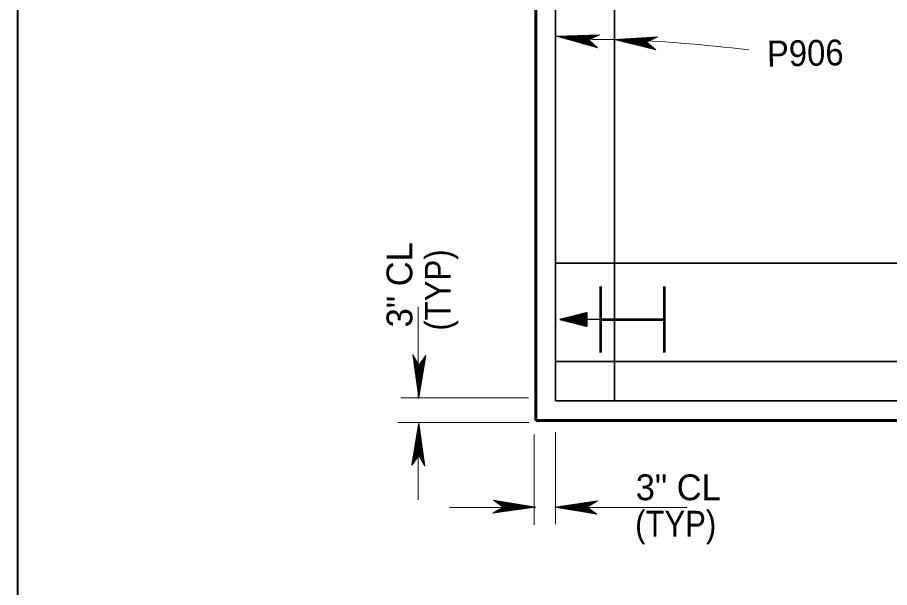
# Model space of a CAD drawing. Extents: x 144 to 252, y 360 to 425.
# Drawn here: x 149.81 to 160.9, y 367.66 to 374.91 of the extents above; entities that cross this region are included whole.
import ezdxf
from ezdxf.enums import TextEntityAlignment as Align

# ---------------------------------------------------------------- set-up
doc = ezdxf.new("R2010")
doc.units = 0
doc.header["$LTSCALE"] = 0.13
for name, color, linetype, lineweight in [('1', 7, 'Continuous', 40), ('10', 7, 'Continuous', 35), ('16', 7, 'Continuous', 13), ('3', 7, 'Continuous', 13), ('9', 7, 'Continuous', 25)]:
    doc.layers.add(name, color=color, linetype=linetype, lineweight=lineweight)

msp = doc.modelspace()

# ---------------------------------------------------------------- linework, layer by layer
at = {"layer": '1', "lineweight": 60}
for p, q in [((156.4041, 369.7844), (156.4041, 379.7844)), ((156.4041, 376.5865), (156.4041, 371.7844)), ((156.4041, 374.4416), (156.4041, 369.7844)), ((156.4041, 372.0416), (156.4041, 373.7844)), ((156.4041, 372.362), (156.4041, 369.7844)), ((156.4041, 372.362), (156.4041, 369.7844)), ((156.4041, 369.7844), (180.4041, 369.7844)), ((156.4041, 369.7844), (180.4041, 369.7844)), ((156.4041, 369.7844), (180.4041, 369.7844)), ((156.4041, 369.7844), (180.4041, 369.7844)), ((156.4041, 369.7844), (180.4041, 369.7844))]:
    msp.add_line(p, q, dxfattribs=at)
at = {"layer": '1', "lineweight": 35}
for p, q in [((156.6541, 377.2068), (156.6541, 373.7844)), ((157.4041, 377.2068), (157.4041, 373.7844)), ((156.6541, 372.362), (156.6541, 373.7844)), ((157.4041, 372.362), (157.4041, 373.7844)), ((156.6541, 372.362), (156.6541, 370.0344)), ((157.4041, 372.362), (157.4041, 370.0344)), ((156.6541, 371.7844), (168.4097, 371.7844)), ((156.6541, 370.5344), (168.3923, 370.5344)), ((156.6541, 370.0344), (168.3923, 370.0344))]:
    msp.add_line(p, q, dxfattribs=at)
at = {"layer": '1', "lineweight": 53}
for p, q in [((157.2267, 371.4886), (157.2267, 370.649)), ((158.0351, 371.4885), (158.0351, 370.6489)), ((157.2267, 371.0687), (158.0351, 371.0687))]:
    msp.add_line(p, q, dxfattribs=at)
at = {"layer": '1', "lineweight": 13}
for p, q in [((154.9073, 370.0656), (154.9073, 371.2288)), ((154.9073, 368.7763), (154.9073, 369.6027)), ((156.3804, 368.6813), (155.3042, 368.6813)), ((158.3215, 368.6813), (156.7543, 368.6813))]:
    msp.add_line(p, q, dxfattribs=at)
at = {"layer": '1', "lineweight": 25}
msp.add_line((157.2267, 371.0687), (156.7267, 371.0687), dxfattribs=at)
at = {"layer": '1'}
msp.add_lwpolyline([(250.3172, 361.9183), (250.3172, 423.9913), (149.8112, 423.9913), (149.8112, 361.9183), (230.3642, 361.9183)], dxfattribs=at)
at = {"layer": '10'}
for p, q in [((157.0489, 371.0683), (156.7137, 371.0683)), ((156.865, 371.0534), (157.0489, 371.0457)), ((156.8651, 371.0598), (157.0489, 371.052)), ((157.0489, 371.0583), (156.8653, 371.066)), ((156.8654, 371.0722), (157.0489, 371.0646)), ((157.0489, 371.0206), (156.8763, 371.0278))]:
    msp.add_line(p, q, dxfattribs=at)
for points in [[(157.0489, 371.1518), (157.0489, 370.9849), (156.7137, 371.0682)], [(157.0489, 371.1518), (156.7137, 371.0682), (157.0489, 371.1518)]]:
    msp.add_lwpolyline(points, dxfattribs=at)
msp.add_lwpolyline([(156.7137, 371.0682), (157.0489, 371.1518), (157.0489, 370.9849), (157.0489, 371.1518)], close=True, dxfattribs=at)
at = {"layer": '16'}
for centre, radius, start, end in [((157.2604, 378.6749), 4.0492, 261.51424, 271.97762), ((156.8168, 356.2312), 18.4061, 82.84501, 88.18371)]:
    msp.add_arc(centre, radius, start, end, dxfattribs=at)
at = {"layer": '3'}
for p, q in [((157.2168, 374.6876), (156.6629, 374.67)), ((156.6629, 374.67), (157.1877, 374.5227)), ((157.0758, 374.6248), (156.6629, 374.67)), ((157.2105, 374.6848), (156.6772, 374.6678)), ((156.6772, 374.6678), (157.1847, 374.5254)), ((157.2068, 374.6831), (156.6879, 374.6666)), ((156.6879, 374.6666), (157.1817, 374.5281)), ((157.202, 374.681), (156.7022, 374.665)), ((156.7022, 374.665), (157.1778, 374.5317)), ((157.1977, 374.679), (156.7149, 374.6637)), ((157.1977, 374.679), (156.7149, 374.6637)), ((156.7149, 374.6637), (157.1744, 374.5347)), ((157.1937, 374.6773), (156.7262, 374.6624)), ((156.7262, 374.6624), (157.1713, 374.5375)), ((157.1889, 374.6751), (156.7406, 374.6608)), ((156.7406, 374.6608), (157.1675, 374.5412)), ((157.1846, 374.6732), (156.7533, 374.6594)), ((156.7533, 374.6594), (157.1641, 374.5442)), ((157.1799, 374.6712), (156.7669, 374.6579)), ((156.7669, 374.6579), (157.1603, 374.5476)), ((157.1753, 374.6691), (156.7807, 374.6564)), ((156.7807, 374.6564), (157.1566, 374.5511)), ((157.1707, 374.667), (156.7938, 374.655)), ((156.7938, 374.655), (157.153, 374.5543)), ((157.166, 374.6648), (156.8077, 374.6535)), ((156.8077, 374.6535), (157.1492, 374.5577)), ((157.1618, 374.6631), (156.8202, 374.6521)), ((156.8202, 374.6521), (157.1458, 374.5607)), ((157.1578, 374.6612), (156.8315, 374.6508)), ((156.8315, 374.6508), (157.1427, 374.5637)), ((157.1526, 374.659), (156.8471, 374.6492)), ((156.8471, 374.6492), (157.1385, 374.5674)), ((157.1478, 374.6568), (156.8608, 374.6477)), ((156.8608, 374.6477), (157.1347, 374.5709)), ((157.1403, 374.6534), (156.8787, 374.6452)), ((156.8787, 374.6452), (157.1308, 374.5744)), ((157.1437, 374.655), (156.8804, 374.6466)), ((157.1356, 374.6513), (156.8925, 374.6437)), ((156.8925, 374.6437), (157.1271, 374.5778)), ((157.1311, 374.6493), (156.9056, 374.6422)), ((156.9056, 374.6422), (157.1236, 374.5811)), ((157.1295, 374.6487), (156.9147, 374.6418)), ((156.9147, 374.6418), (157.1202, 374.5842)), ((157.1254, 374.6468), (156.9266, 374.6404)), ((156.9266, 374.6404), (157.1168, 374.5872)), ((157.1207, 374.6447), (156.9403, 374.6389)), ((156.9403, 374.6389), (157.1131, 374.5906)), ((157.1154, 374.6424), (156.9559, 374.6372)), ((156.9559, 374.6372), (157.1088, 374.5943)), ((157.1111, 374.6404), (156.9684, 374.6358)), ((156.9684, 374.6358), (157.1055, 374.5975)), ((157.1066, 374.6384), (156.9816, 374.6344)), ((156.9816, 374.6344), (157.1019, 374.6008)), ((157.1026, 374.6366), (156.9935, 374.6331)), ((156.9935, 374.6331), (157.0987, 374.6037)), ((157.0977, 374.6345), (157.0079, 374.6316)), ((157.0079, 374.6316), (157.0948, 374.6072)), ((157.093, 374.6324), (157.0217, 374.63)), ((157.0217, 374.63), (157.0909, 374.6107)), ((157.0887, 374.6305), (157.0342, 374.6287)), ((157.0342, 374.6287), (157.0876, 374.6137)), ((157.0475, 374.6273), (157.084, 374.617)), ((157.0831, 374.628), (157.0577, 374.6272)), ((157.0803, 374.6268), (157.0588, 374.626)), ((157.0588, 374.626), (157.0808, 374.6198)), ((157.0689, 374.6248), (157.0781, 374.6223)), ((157.0756, 374.6247), (157.2168, 374.6876)), ((157.1877, 374.5227), (157.0756, 374.6247)), ((157.9533, 374.6627), (157.4002, 374.6281)), ((157.4002, 374.6281), (157.9292, 374.4971)), ((157.8143, 374.5956), (157.4002, 374.6281)), ((157.9471, 374.6597), (157.4145, 374.6262)), ((157.4145, 374.6262), (157.9262, 374.4997)), ((157.9434, 374.6579), (157.4253, 374.6254)), ((157.4253, 374.6254), (157.9231, 374.5023)), ((157.9387, 374.6557), (157.4397, 374.6243)), ((157.4397, 374.6243), (157.9191, 374.5057)), ((157.9344, 374.6536), (157.4523, 374.6233)), ((157.9344, 374.6536), (157.4523, 374.6233)), ((157.4523, 374.6233), (157.9156, 374.5087)), ((157.9306, 374.6517), (157.4637, 374.6224)), ((157.4637, 374.6224), (157.9124, 374.5113)), ((157.9257, 374.6493), (157.4781, 374.6213)), ((157.4781, 374.6213), (157.9084, 374.5148)), ((157.9215, 374.6472), (157.4907, 374.6203)), ((157.4907, 374.6203), (157.9049, 374.5178)), ((157.9169, 374.6452), (157.5045, 374.6192)), ((157.5045, 374.6192), (157.9011, 374.5211)), ((157.9123, 374.6429), (157.5182, 374.6182)), ((157.5182, 374.6182), (157.8972, 374.5244)), ((157.9079, 374.6407), (157.5315, 374.6171)), ((157.5315, 374.6171), (157.8936, 374.5275)), ((157.9032, 374.6384), (157.5453, 374.616)), ((157.5453, 374.616), (157.8897, 374.5308)), ((157.899, 374.6365), (157.5579, 374.6151)), ((157.5579, 374.6151), (157.8862, 374.5337)), ((157.8951, 374.6346), (157.5692, 374.6142)), ((157.5692, 374.6142), (157.883, 374.5366)), ((157.8899, 374.6322), (157.5849, 374.6129)), ((157.5849, 374.6129), (157.8787, 374.5403)), ((157.8852, 374.6298), (157.5987, 374.6118)), ((157.5987, 374.6118), (157.8748, 374.5435)), ((157.8778, 374.6262), (157.6166, 374.6099)), ((157.6166, 374.6099), (157.8708, 374.5469)), ((157.8811, 374.6279), (157.6182, 374.6114)), ((157.8732, 374.624), (157.6304, 374.6088)), ((157.6304, 374.6088), (157.8669, 374.5503)), ((157.8688, 374.6218), (157.6436, 374.6078)), ((157.6436, 374.6078), (157.8633, 374.5534)), ((157.8672, 374.6211), (157.6527, 374.6076)), ((157.6527, 374.6076), (157.8598, 374.5564)), ((157.8632, 374.6192), (157.6647, 374.6067)), ((157.6647, 374.6067), (157.8564, 374.5592)), ((157.8585, 374.6168), (157.6784, 374.6056)), ((157.6784, 374.6056), (157.8526, 374.5626)), ((157.8533, 374.6144), (157.6941, 374.6043)), ((157.6941, 374.6043), (157.8482, 374.5662)), ((157.8491, 374.6123), (157.7066, 374.6034)), ((157.7066, 374.6034), (157.8448, 374.5693)), ((157.8447, 374.6102), (157.7198, 374.6023)), ((157.7198, 374.6023), (157.8411, 374.5723)), ((157.8407, 374.6082), (157.7318, 374.6014)), ((157.7318, 374.6014), (157.8377, 374.5752)), ((157.8357, 374.6059), (157.7463, 374.6002)), ((157.7463, 374.6002), (157.8337, 374.5786)), ((157.8312, 374.6037), (157.76, 374.5992)), ((157.76, 374.5992), (157.8297, 374.5819)), ((157.8269, 374.6017), (157.7727, 374.5982)), ((157.7727, 374.5982), (157.8263, 374.5849)), ((157.8214, 374.5991), (157.7962, 374.5974)), ((157.8187, 374.5977), (157.7972, 374.5962)), ((157.8141, 374.5954), (157.9533, 374.6627)), ((157.7858, 374.5972), (157.8227, 374.5881)), ((157.7972, 374.5962), (157.8194, 374.5908)), ((157.8073, 374.5955), (157.8167, 374.5933)), ((157.9292, 374.4971), (157.8141, 374.5954)), ((154.8376, 370.6215), (154.9153, 370.0727)), ((154.9155, 370.4879), (154.8376, 370.6215)), ((154.8411, 370.6155), (154.916, 370.0872)), ((154.8431, 370.612), (154.916, 370.098)), ((154.8457, 370.6074), (154.916, 370.1124)), ((154.9153, 370.0727), (155.0046, 370.6104)), ((155.0046, 370.6104), (154.9155, 370.4879)), ((154.916, 370.0872), (155.0023, 370.6072)), ((154.8482, 370.6033), (154.916, 370.1252)), ((154.8482, 370.6033), (154.916, 370.1252)), ((154.8503, 370.5997), (154.916, 370.1365)), ((154.853, 370.5951), (154.916, 370.1509)), ((154.8554, 370.591), (154.916, 370.1637)), ((154.8579, 370.5866), (154.916, 370.1774)), ((154.8605, 370.5822), (154.916, 370.1912)), ((154.863, 370.5779), (154.916, 370.2045)), ((154.8657, 370.5734), (154.916, 370.2184)), ((154.8679, 370.5694), (154.916, 370.231)), ((154.8702, 370.5657), (154.916, 370.2424)), ((154.873, 370.5607), (154.916, 370.2581)), ((154.8757, 370.5562), (154.916, 370.2719)), ((154.8779, 370.5523), (154.9149, 370.2915)), ((154.8798, 370.5491), (154.9165, 370.2899)), ((154.8824, 370.5447), (154.9165, 370.3038)), ((154.8849, 370.5404), (154.9165, 370.317)), ((154.8858, 370.5389), (154.916, 370.3261)), ((154.888, 370.535), (154.916, 370.3381)), ((154.8907, 370.5306), (154.916, 370.3519)), ((154.8935, 370.5256), (154.916, 370.3676)), ((154.8959, 370.5215), (154.916, 370.3802)), ((154.8984, 370.5172), (154.916, 370.3934)), ((154.9007, 370.5134), (154.916, 370.4054)), ((154.9033, 370.5087), (154.916, 370.4199)), ((154.9059, 370.5043), (154.916, 370.4337)), ((154.9082, 370.5002), (154.916, 370.4464)), ((154.9113, 370.495), (154.9149, 370.4699)), ((154.916, 370.098), (154.9999, 370.6039)), ((154.916, 370.1124), (154.9967, 370.5997)), ((154.916, 370.1252), (154.9941, 370.5959)), ((154.916, 370.1365), (154.9917, 370.5926)), ((154.916, 370.1509), (154.9885, 370.5883)), ((154.916, 370.1637), (154.9857, 370.5846)), ((154.916, 370.1774), (154.9828, 370.5805)), ((154.916, 370.1912), (154.9798, 370.5764)), ((154.916, 370.2045), (154.977, 370.5725)), ((154.916, 370.2184), (154.974, 370.5684)), ((154.916, 370.231), (154.9713, 370.5647)), ((154.916, 370.2424), (154.9688, 370.5612)), ((154.916, 370.2581), (154.9655, 370.5567)), ((154.916, 370.2719), (154.9625, 370.5526)), ((154.916, 370.3261), (154.9508, 370.5366)), ((154.916, 370.3381), (154.9483, 370.533)), ((154.916, 370.3519), (154.9452, 370.5289)), ((154.916, 370.3676), (154.942, 370.5242)), ((154.916, 370.3802), (154.9392, 370.5206)), ((154.916, 370.3934), (154.9364, 370.5167)), ((154.916, 370.4054), (154.9338, 370.5131)), ((154.916, 370.4199), (154.9307, 370.5088)), ((154.916, 370.4337), (154.9278, 370.5047)), ((154.916, 370.4464), (154.925, 370.501)), ((154.916, 370.4597), (154.9222, 370.4971)), ((154.9165, 370.2899), (154.9594, 370.5483)), ((154.9165, 370.3038), (154.9564, 370.5442)), ((154.9165, 370.317), (154.9536, 370.5403)), ((154.9129, 370.4923), (154.916, 370.4711)), ((154.9153, 370.4882), (154.9153, 370.0727)), ((154.916, 370.4711), (154.9197, 370.4937)), ((154.916, 370.4812), (154.9175, 370.4907)), ((156.3099, 370.0731), (154.6842, 370.0731)), ((156.3131, 369.7587), (154.6467, 369.7587)), ((154.9135, 369.7547), (154.8243, 369.217)), ((154.9128, 369.7403), (154.8266, 369.2202)), ((154.9128, 369.7294), (154.8289, 369.2235)), ((154.9878, 369.2119), (154.9128, 369.7403)), ((154.9857, 369.2154), (154.9128, 369.7294)), ((154.9135, 369.3392), (154.9135, 369.7547)), ((154.9913, 369.2059), (154.9135, 369.7547)), ((154.9128, 369.715), (154.8321, 369.2278)), ((154.9128, 369.7022), (154.8347, 369.2315)), ((154.9128, 369.6909), (154.8372, 369.2348)), ((154.9128, 369.6765), (154.8403, 369.2391)), ((154.9128, 369.6637), (154.8431, 369.2428)), ((154.9128, 369.65), (154.846, 369.2469)), ((154.9128, 369.6362), (154.849, 369.251)), ((154.9128, 369.6229), (154.8518, 369.2549)), ((154.9128, 369.609), (154.8548, 369.259)), ((154.9831, 369.22), (154.9128, 369.715)), ((154.9807, 369.2241), (154.9128, 369.7022)), ((154.9807, 369.2241), (154.9128, 369.7022)), ((154.9785, 369.2278), (154.9128, 369.6909)), ((154.9758, 369.2323), (154.9128, 369.6765)), ((154.9734, 369.2364), (154.9128, 369.6637)), ((154.9709, 369.2408), (154.9128, 369.65)), ((154.9683, 369.2452), (154.9128, 369.6362)), ((154.9658, 369.2495), (154.9128, 369.6229)), ((154.9632, 369.254), (154.9128, 369.609)), ((156.6541, 368.4697), (156.6541, 369.6374)), ((154.9128, 369.5964), (154.8575, 369.2627)), ((154.9128, 369.585), (154.86, 369.2662)), ((154.9128, 369.5693), (154.8633, 369.2707)), ((154.9128, 369.5555), (154.8663, 369.2748)), ((154.9123, 369.5375), (154.8694, 369.2791)), ((154.9123, 369.5236), (154.8724, 369.2833)), ((154.9123, 369.5104), (154.8752, 369.2871)), ((154.9128, 369.5013), (154.878, 369.2908)), ((154.949, 369.2783), (154.9123, 369.5375)), ((154.9464, 369.2827), (154.9123, 369.5236)), ((154.9439, 369.287), (154.9123, 369.5104)), ((154.9609, 369.258), (154.9128, 369.5964)), ((154.9587, 369.2618), (154.9128, 369.585)), ((154.9558, 369.2668), (154.9128, 369.5693)), ((154.9532, 369.2712), (154.9128, 369.5555)), ((154.9431, 369.2885), (154.9128, 369.5013)), ((154.9509, 369.2752), (154.9139, 369.5359)), ((156.3818, 368.4615), (156.3818, 369.6063)), ((154.9128, 369.4893), (154.8806, 369.2944)), ((154.9128, 369.4755), (154.8836, 369.2985)), ((154.9128, 369.4598), (154.8868, 369.3032)), ((154.9128, 369.4472), (154.8896, 369.3068)), ((154.9128, 369.434), (154.8924, 369.3107)), ((154.9128, 369.422), (154.8951, 369.3143)), ((154.9128, 369.4075), (154.8981, 369.3186)), ((154.9128, 369.3937), (154.9011, 369.3227)), ((154.9408, 369.2924), (154.9128, 369.4893)), ((154.9382, 369.2968), (154.9128, 369.4755)), ((154.9353, 369.3018), (154.9128, 369.4598)), ((154.9329, 369.3059), (154.9128, 369.4472)), ((154.9304, 369.3102), (154.9128, 369.434)), ((154.9282, 369.314), (154.9128, 369.422)), ((154.9255, 369.3187), (154.9128, 369.4075)), ((154.9229, 369.3231), (154.9128, 369.3937)), ((154.8243, 369.217), (154.9133, 369.3395)), ((154.9128, 369.381), (154.9038, 369.3264)), ((154.9128, 369.3678), (154.9067, 369.3303)), ((154.9128, 369.3563), (154.9091, 369.3338)), ((154.9128, 369.3462), (154.9113, 369.3367)), ((154.9206, 369.3272), (154.9128, 369.381)), ((154.9159, 369.3351), (154.9128, 369.3563)), ((154.9133, 369.3395), (154.9913, 369.2059)), ((154.9175, 369.3324), (154.9139, 369.3575)), ((156.4008, 368.6837), (155.8632, 368.773)), ((155.8632, 368.773), (155.9857, 368.6839)), ((156.3864, 368.6844), (155.8664, 368.7707)), ((156.3756, 368.6844), (155.8697, 368.7683)), ((156.3612, 368.6844), (155.8739, 368.7652)), ((156.3484, 368.6844), (155.8777, 368.7625)), ((156.3371, 368.6844), (155.881, 368.7601)), ((156.3227, 368.6844), (155.8852, 368.7569)), ((156.3099, 368.6844), (155.889, 368.7542)), ((156.2962, 368.6844), (155.8931, 368.7512)), ((156.2823, 368.6844), (155.8972, 368.7482)), ((156.2691, 368.6844), (155.9011, 368.7454)), ((156.2552, 368.6844), (155.9052, 368.7424)), ((156.2426, 368.6844), (155.9089, 368.7398)), ((156.2312, 368.6844), (155.9123, 368.7372)), ((156.2155, 368.6844), (155.9169, 368.7339)), ((156.2017, 368.6844), (155.921, 368.7309)), ((156.1837, 368.6849), (155.9253, 368.7278)), ((156.1697, 368.6849), (155.9294, 368.7248)), ((156.1566, 368.6849), (155.9332, 368.722)), ((157.1884, 368.7632), (156.6397, 368.6855)), ((157.1824, 368.7597), (156.6541, 368.6848)), ((157.1789, 368.7577), (156.6649, 368.6848)), ((157.1743, 368.7551), (156.6793, 368.6848)), ((157.1702, 368.7527), (156.6921, 368.6848)), ((157.1702, 368.7527), (156.6921, 368.6848)), ((157.1666, 368.7505), (156.7034, 368.6848)), ((157.162, 368.7478), (156.7178, 368.6848)), ((157.1579, 368.7454), (156.7306, 368.6848)), ((157.1535, 368.7429), (156.7443, 368.6848)), ((157.1491, 368.7403), (156.7582, 368.6848)), ((157.1448, 368.7378), (156.7714, 368.6848)), ((157.1403, 368.7352), (156.7853, 368.6848)), ((157.1363, 368.7329), (156.7979, 368.6848)), ((157.1326, 368.7307), (156.8093, 368.6848)), ((157.1276, 368.7278), (156.825, 368.6848)), ((157.1232, 368.7252), (156.8388, 368.6848)), ((157.116, 368.721), (156.8568, 368.6843)), ((157.1192, 368.7229), (156.8584, 368.6859)), ((157.0548, 368.6853), (157.1884, 368.7632)), ((155.9857, 368.6839), (155.8521, 368.606)), ((155.8521, 368.606), (156.4008, 368.6837)), ((155.8581, 368.6095), (156.3864, 368.6844)), ((155.8616, 368.6115), (156.3756, 368.6844)), ((155.8662, 368.6142), (156.3612, 368.6844)), ((155.8702, 368.6166), (156.3484, 368.6844)), ((155.8702, 368.6166), (156.3484, 368.6844)), ((155.8739, 368.6187), (156.3371, 368.6844)), ((155.8785, 368.6214), (156.3227, 368.6844)), ((155.8826, 368.6238), (156.3099, 368.6844)), ((155.887, 368.6263), (156.2962, 368.6844)), ((155.8914, 368.6289), (156.2823, 368.6844)), ((155.8957, 368.6314), (156.2691, 368.6844)), ((155.9002, 368.6341), (156.2552, 368.6844)), ((155.9042, 368.6363), (156.2426, 368.6844)), ((155.9079, 368.6386), (156.2312, 368.6844)), ((155.9129, 368.6414), (156.2155, 368.6844)), ((155.9173, 368.6441), (156.2017, 368.6844)), ((155.9213, 368.6463), (156.1821, 368.6833)), ((155.9245, 368.6482), (156.1837, 368.6849)), ((155.9289, 368.6508), (156.1697, 368.6849)), ((155.9332, 368.6533), (156.1566, 368.6849)), ((155.9347, 368.6542), (156.1475, 368.6844)), ((156.1475, 368.6844), (155.937, 368.7192)), ((155.9386, 368.6564), (156.1355, 368.6844)), ((156.1355, 368.6844), (155.9406, 368.7167)), ((155.943, 368.6591), (156.1217, 368.6844)), ((156.1217, 368.6844), (155.9447, 368.7137)), ((155.948, 368.6619), (156.106, 368.6844)), ((156.106, 368.6844), (155.9493, 368.7104)), ((155.9521, 368.6643), (156.0934, 368.6844)), ((156.0934, 368.6844), (155.953, 368.7077)), ((155.9563, 368.6668), (156.0802, 368.6844)), ((156.0802, 368.6844), (155.9569, 368.7048)), ((155.9602, 368.6691), (156.0682, 368.6844)), ((156.0682, 368.6844), (155.9605, 368.7022)), ((156.0537, 368.6844), (155.9647, 368.6992)), ((155.9648, 368.6717), (156.0537, 368.6844)), ((156.0398, 368.6844), (155.9689, 368.6962)), ((155.9692, 368.6743), (156.0398, 368.6844)), ((156.0272, 368.6844), (155.9726, 368.6934)), ((155.9733, 368.6767), (156.0272, 368.6844)), ((156.0139, 368.6844), (155.9765, 368.6906)), ((155.9786, 368.6798), (156.0037, 368.6833)), ((156.0025, 368.6844), (155.9799, 368.6882)), ((155.9812, 368.6813), (156.0025, 368.6844)), ((155.9923, 368.6844), (155.9829, 368.6859)), ((155.9854, 368.6837), (156.4008, 368.6837)), ((156.6397, 368.6855), (157.1773, 368.5962)), ((157.0551, 368.6855), (156.6397, 368.6855)), ((156.6541, 368.6848), (157.1741, 368.5986)), ((156.6649, 368.6848), (157.1708, 368.6009)), ((156.6793, 368.6848), (157.1666, 368.6041)), ((156.6921, 368.6848), (157.1628, 368.6067)), ((156.7034, 368.6848), (157.1595, 368.6092)), ((156.7178, 368.6848), (157.1552, 368.6123)), ((156.7306, 368.6848), (157.1515, 368.6151)), ((156.7443, 368.6848), (157.1474, 368.618)), ((156.7582, 368.6848), (157.1433, 368.621)), ((156.7714, 368.6848), (157.1394, 368.6238)), ((156.7853, 368.6848), (157.1353, 368.6268)), ((156.7979, 368.6848), (157.1316, 368.6295)), ((156.8093, 368.6848), (157.1282, 368.632)), ((156.825, 368.6848), (157.1236, 368.6353)), ((156.8388, 368.6848), (157.1195, 368.6383)), ((156.8568, 368.6843), (157.1153, 368.6414)), ((157.1116, 368.7184), (156.8707, 368.6843)), ((156.8707, 368.6843), (157.1111, 368.6444)), ((157.1073, 368.7159), (156.8839, 368.6843)), ((156.8839, 368.6843), (157.1072, 368.6472)), ((157.1058, 368.7151), (156.893, 368.6848)), ((156.893, 368.6848), (157.1035, 368.65)), ((157.1019, 368.7128), (156.905, 368.6848)), ((156.905, 368.6848), (157.0999, 368.6526)), ((157.0975, 368.7102), (156.9188, 368.6848)), ((156.9188, 368.6848), (157.0958, 368.6556)), ((157.0925, 368.7073), (156.9345, 368.6848)), ((156.9345, 368.6848), (157.0912, 368.6588)), ((157.0884, 368.7049), (156.9471, 368.6848)), ((156.9471, 368.6848), (157.0875, 368.6616)), ((157.0842, 368.7024), (156.9603, 368.6848)), ((156.9603, 368.6848), (157.0836, 368.6644)), ((157.0803, 368.7002), (156.9723, 368.6848)), ((156.9723, 368.6848), (157.08, 368.6671)), ((157.0757, 368.6975), (156.9868, 368.6848)), ((156.9868, 368.6848), (157.0757, 368.6701)), ((157.0712, 368.6949), (157.0007, 368.6848)), ((157.0007, 368.6848), (157.0716, 368.6731)), ((157.0672, 368.6926), (157.0133, 368.6848)), ((157.0133, 368.6848), (157.0679, 368.6758)), ((157.0266, 368.6848), (157.064, 368.6787)), ((157.0619, 368.6895), (157.0368, 368.6859)), ((157.0592, 368.6879), (157.038, 368.6848)), ((157.038, 368.6848), (157.0606, 368.6811)), ((157.0482, 368.6848), (157.0576, 368.6833)), ((157.1773, 368.5962), (157.0548, 368.6853))]:
    msp.add_line(p, q, dxfattribs=at)
at = {"layer": '9'}
for p, q in [((156.7243, 371.0656), (156.8651, 371.0598)), ((156.7277, 371.0718), (156.8653, 371.066)), ((156.7493, 371.0772), (156.8654, 371.0722)), ((156.7548, 371.0581), (156.865, 371.0534)), ((156.7709, 371.0825), (156.8656, 371.0786)), ((156.7852, 371.0505), (156.8648, 371.0472)), ((156.7925, 371.0879), (156.8657, 371.0848)), ((156.8141, 371.0933), (156.8659, 371.0912)), ((156.8357, 371.0987), (156.8661, 371.0974)), ((156.8573, 371.104), (156.8663, 371.1037)), ((156.8656, 371.0786), (157.0489, 371.0709)), ((156.8657, 371.0848), (157.0489, 371.0772)), ((156.8659, 371.0912), (157.0489, 371.0834)), ((156.8661, 371.0974), (157.0489, 371.0897)), ((156.8663, 371.1037), (157.0489, 371.0961)), ((156.8789, 371.1094), (157.0489, 371.1023)), ((156.9005, 371.1148), (157.0489, 371.1086)), ((156.9221, 371.1202), (157.0489, 371.1149)), ((156.9437, 371.1256), (157.0489, 371.1212)), ((156.9652, 371.131), (157.0489, 371.1275)), ((156.9868, 371.1363), (157.0489, 371.1337)), ((157.0085, 371.1418), (157.0489, 371.1401)), ((157.0301, 371.1472), (157.0489, 371.1463)), ((156.8155, 371.0429), (156.8647, 371.0409)), ((156.8459, 371.0353), (156.8645, 371.0346)), ((156.8645, 371.0346), (157.0489, 371.0268)), ((156.8647, 371.0409), (157.0489, 371.0332)), ((156.8648, 371.0472), (157.0489, 371.0395)), ((156.9067, 371.0202), (157.0489, 371.0143)), ((156.9371, 371.0127), (157.0489, 371.008)), ((156.9675, 371.0052), (157.0489, 371.0018)), ((156.9979, 370.9976), (157.0489, 370.9954)), ((157.0282, 370.99), (157.0489, 370.9892))]:
    msp.add_line(p, q, dxfattribs=at)
at = {"layer": '9', "lineweight": 40}
msp.add_lwpolyline([(156.7137, 371.0682), (157.0489, 371.1518), (157.0489, 370.9849)], close=True, dxfattribs=at)

# ---------------------------------------------------------------- texts
at = {"layer": '16', "width": 0.95}
msp.add_text('P906', height=0.3281, rotation=1, dxfattribs=at).set_placement((159.3451, 374.283))
at = {"layer": '16'}
msp.add_text('3" CL', height=0.3281, rotation=90, dxfattribs=at).set_placement((154.8324, 372.0517), align=Align.RIGHT)
at = {"layer": '16', "width": 0.9}
msp.add_text('(TYP)', height=0.3281, rotation=90, dxfattribs=at).set_placement((155.32, 371.9595), align=Align.RIGHT)
at = {"layer": '16'}
msp.add_text('3" CL', height=0.3281, dxfattribs=at).set_placement((157.6728, 368.7726))
at = {"layer": '16', "width": 0.9}
msp.add_text('(TYP)', height=0.3281, dxfattribs=at).set_placement((157.6656, 368.3097))

doc.saveas('drawing.dxf')
